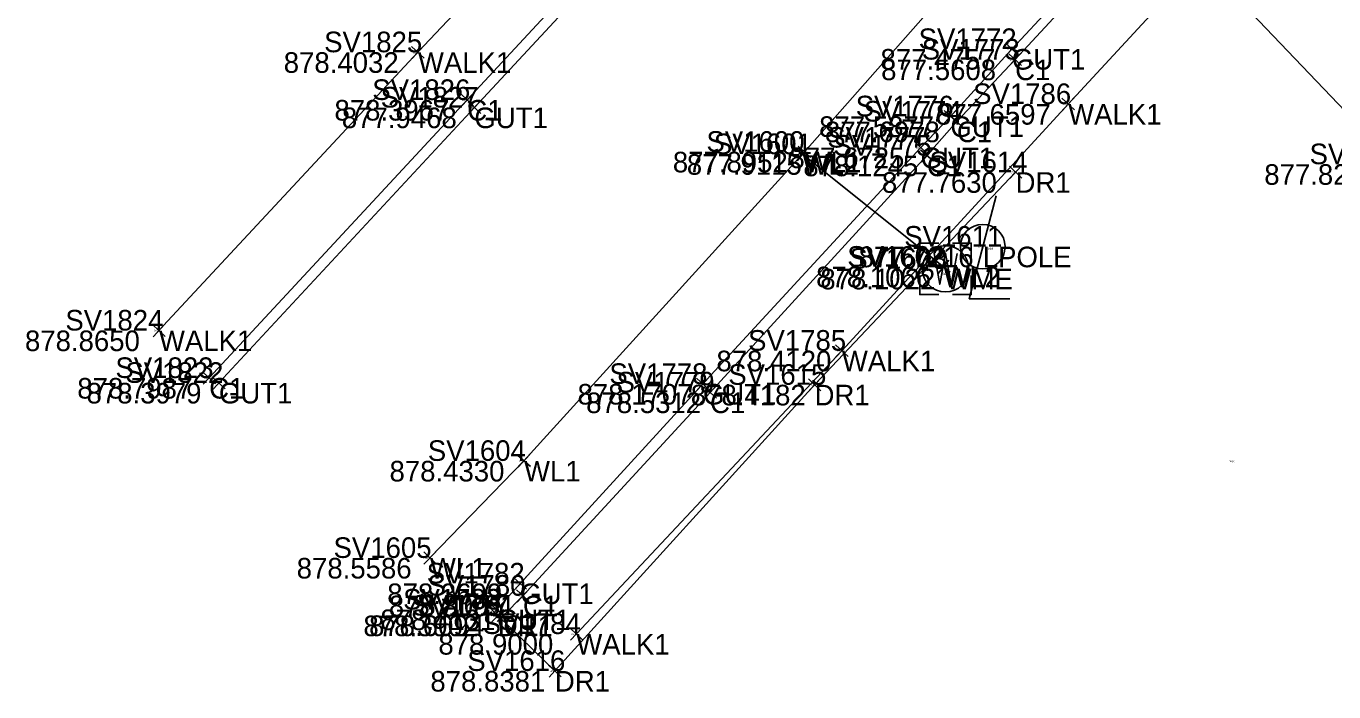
# Model space of a CAD drawing. Extents: x 1469677 to 1493262, y 375219 to 389293.
# Drawn here: x 1480027.7 to 1480103.9, y 379268.2 to 379307 of the extents above; entities that cross this region are included whole.
import ezdxf

# ---------------------------------------------------------------- set-up
doc = ezdxf.new("R2010")
doc.units = 0
for name, color, linetype in [('DR_X_Drive_Pipe', 7, 'Continuous'), ('DV_X_Lot_Line', 7, 'Continuous'), ('DV_X_Text', 7, 'Continuous'), ('GK_Visualization', 7, 'Continuous'), ('PNTDESC', 7, 'Continuous'), ('PNTELEV', 7, 'Continuous'), ('PNTNO', 7, 'Continuous'), ('RD_P_Text', 7, 'Continuous'), ('RW_P_Esmt_SW', 7, 'Continuous'), ('Text Border', 7, 'Continuous')]:
    doc.layers.add(name, color=color, linetype=linetype)

msp = doc.modelspace()

# ---------------------------------------------------------------- linework, layer by layer
at = {"layer": 'DR_X_Drive_Pipe'}
for points in [[(1480169.204, 379397.823), (1480165.761, 379394.087), (1480162.59, 379391.88), (1480159.156, 379388.706), (1480148.911, 379378.819), (1480120.344, 379350.087), (1480106.297, 379335.736), (1480080.736, 379308.289), (1480073.091, 379299.637), (1480056.748, 379281.628), (1480051.266, 379275.974)], [(1480072.97, 379299.499), (1480081.181, 379292.941)]]:
    msp.add_lwpolyline(points, dxfattribs=at)
at = {"layer": 'DV_X_Lot_Line'}
for points in [[(1480035.484, 379289.224), (1480050.568, 379305.437), (1480062.335, 379317.896), (1480064.038, 379319.719), (1480070.805, 379327.066), (1480078.054, 379334.946), (1480079.953, 379336.866), (1480094.208, 379352.393), (1480112.048, 379371.575), (1480117.348, 379377.211), (1480119.911, 379379.906), (1480121.511, 379381.77), (1480134.604, 379395.58), (1480136.695, 379398.148), (1480138.778, 379401.149), (1480140.004, 379404.725), (1480140.577, 379408.06), (1480140.982, 379411.311), (1480140.871, 379414.584), (1480140.225, 379417.636), (1480139.184, 379419.586), (1480133.124, 379425.845), (1480132.903, 379425.968), (1480114.834, 379442.96)], [(1480059.793, 379271.54), (1480075.261, 379288.048), (1480088.444, 379302.419), (1480096.088, 379310.695), (1480098.33, 379313.163), (1480111.975, 379327.613), (1480128.977, 379345.933), (1480145.46, 379363.52), (1480153.413, 379372.021), (1480155.772, 379374.786), (1480158.213, 379377.107), (1480160.137, 379378.801), (1480161.631, 379379.994)]]:
    msp.add_lwpolyline(points, dxfattribs=at)
at = {"layer": 'PNTDESC'}
msp.add_lwpolyline([(1480084.257, 379297.063), (1480082.682, 379291.078), (1480085.046, 379291.078)], dxfattribs=at)
msp.add_circle((1480083.471, 379294.11), 1.3, dxfattribs=at)
at = {"layer": 'PNTELEV'}
for p, q in [((1480050.202, 379305.777), (1480050.934, 379305.096)), ((1480050.227, 379305.071), (1480050.909, 379305.803)), ((1480050.568, 379305.437), (1480050.568, 379305.437)), ((1480085.532, 379305.284), (1480084.8, 379305.965)), ((1480085.507, 379305.99), (1480084.825, 379305.258)), ((1480085.723, 379304.67), (1480084.989, 379305.349)), ((1480085.696, 379305.377), (1480085.016, 379304.643)), ((1480085.166, 379305.624), (1480085.166, 379305.624)), ((1480085.356, 379305.01), (1480085.356, 379305.01)), ((1480053.105, 379302.289), (1480053.785, 379303.022)), ((1480053.079, 379302.996), (1480053.811, 379302.315)), ((1480053.445, 379302.656), (1480053.445, 379302.656)), ((1480053.491, 379302.555), (1480054.225, 379301.874)), ((1480053.518, 379301.848), (1480054.198, 379302.581)), ((1480088.076, 379302.757), (1480088.812, 379302.081)), ((1480088.106, 379302.051), (1480088.782, 379302.788)), ((1480088.444, 379302.419), (1480088.444, 379302.419)), ((1480053.858, 379302.215), (1480053.858, 379302.215)), ((1480081.954, 379301.365), (1480081.216, 379302.039)), ((1480081.922, 379302.071), (1480081.248, 379301.332)), ((1480081.585, 379301.702), (1480081.585, 379301.702)), ((1480082.332, 379301.055), (1480081.602, 379301.739)), ((1480082.309, 379301.762), (1480081.625, 379301.032)), ((1480081.967, 379301.397), (1480081.967, 379301.397)), ((1480073.465, 379299.306), (1480072.716, 379299.969)), ((1480073.422, 379300.012), (1480072.76, 379299.263)), ((1480080.216, 379299.537), (1480079.492, 379300.227)), ((1480080.199, 379300.244), (1480079.509, 379299.52)), ((1480072.579, 379299.811), (1480073.36, 379299.187)), ((1480073.282, 379299.889), (1480072.658, 379299.108)), ((1480072.97, 379299.499), (1480072.97, 379299.499)), ((1480073.091, 379299.637), (1480073.091, 379299.637)), ((1480080.593, 379299.082), (1480079.843, 379299.743)), ((1480079.854, 379299.882), (1480079.854, 379299.882)), ((1480080.549, 379299.788), (1480079.887, 379299.038)), ((1480080.218, 379299.413), (1480080.218, 379299.413)), ((1480085.747, 379298.104), (1480085.02, 379298.791)), ((1480085.727, 379298.811), (1480085.04, 379298.084)), ((1480085.383, 379298.448), (1480085.383, 379298.448)), ((1480080.791, 379293.253), (1480081.572, 379292.629)), ((1480081.493, 379293.332), (1480080.869, 379292.55)), ((1480081.181, 379292.941), (1480081.181, 379292.941)), ((1480035.118, 379289.565), (1480035.85, 379288.884)), ((1480035.143, 379288.858), (1480035.825, 379289.59)), ((1480035.484, 379289.224), (1480035.484, 379289.224)), ((1480074.896, 379288.39), (1480075.626, 379287.707)), ((1480074.919, 379287.684), (1480075.603, 379288.413)), ((1480075.261, 379288.048), (1480075.261, 379288.048)), ((1480038.043, 379286.798), (1480038.775, 379286.118)), ((1480038.069, 379286.092), (1480038.749, 379286.824)), ((1480038.409, 379286.458), (1480038.409, 379286.458)), ((1480038.612, 379286.514), (1480039.346, 379285.834)), ((1480038.639, 379285.807), (1480039.319, 379286.541)), ((1480067.54, 379285.772), (1480066.804, 379286.449)), ((1480067.511, 379286.478), (1480066.833, 379285.742)), ((1480074.037, 379285.718), (1480073.311, 379286.405)), ((1480074.017, 379286.425), (1480073.33, 379285.699)), ((1480038.979, 379286.174), (1480038.979, 379286.174)), ((1480067.172, 379286.11), (1480067.172, 379286.11)), ((1480067.958, 379285.276), (1480067.22, 379285.951)), ((1480067.927, 379285.982), (1480067.251, 379285.244)), ((1480067.589, 379285.613), (1480067.589, 379285.613)), ((1480073.674, 379286.062), (1480073.674, 379286.062)), ((1480057.118, 379281.292), (1480056.378, 379281.964)), ((1480057.084, 379281.999), (1480056.412, 379281.258)), ((1480056.748, 379281.628), (1480056.748, 379281.628)), ((1480051.624, 379275.625), (1480050.907, 379276.322)), ((1480051.614, 379276.332), (1480050.917, 379275.615)), ((1480051.266, 379275.974), (1480051.266, 379275.974)), ((1480056.869, 379274.854), (1480056.193, 379274.116)), ((1480056.9, 379274.147), (1480056.162, 379274.823)), ((1480057.056, 379273.435), (1480056.32, 379274.113)), ((1480057.027, 379274.142), (1480056.349, 379273.406)), ((1480056.531, 379274.485), (1480056.531, 379274.485)), ((1480055.541, 379272.635), (1480054.797, 379273.303)), ((1480055.503, 379273.341), (1480054.835, 379272.597)), ((1480056.688, 379273.774), (1480056.688, 379273.774)), ((1480055.577, 379272.265), (1480054.859, 379272.96)), ((1480054.87, 379272.253), (1480055.566, 379272.972)), ((1480055.169, 379272.969), (1480055.169, 379272.969)), ((1480055.902, 379272.271), (1480055.192, 379272.975)), ((1480055.899, 379272.978), (1480055.195, 379272.268)), ((1480055.218, 379272.613), (1480055.218, 379272.613)), ((1480055.547, 379272.623), (1480055.547, 379272.623)), ((1480059.428, 379271.882), (1480060.158, 379271.198)), ((1480059.451, 379271.175), (1480060.135, 379271.905)), ((1480059.793, 379271.54), (1480059.793, 379271.54)), ((1480058.916, 379269.052), (1480058.175, 379269.724)), ((1480058.881, 379269.758), (1480058.21, 379269.018)), ((1480058.546, 379269.388), (1480058.546, 379269.388))]:
    msp.add_line(p, q, dxfattribs=at)
at = {"layer": 'PNTNO'}
msp.add_line((1480081.303, 379292.82), (1480081.303, 379292.82), dxfattribs=at)
for points in [[(1480080.903, 379294.32), (1480079.803, 379294.32), (1480079.803, 379293.22)], [(1480082.803, 379293.22), (1480082.803, 379294.32), (1480081.703, 379294.32)], [(1480080.637, 379293.72), (1480080.97, 379291.92), (1480081.303, 379293.72), (1480081.637, 379291.92), (1480081.97, 379293.72)], [(1480079.803, 379292.42), (1480079.803, 379291.32), (1480080.903, 379291.32)], [(1480081.703, 379291.32), (1480082.803, 379291.32), (1480082.803, 379292.42)]]:
    msp.add_lwpolyline(points, dxfattribs=at)
msp.add_circle((1480081.303, 379292.82), 1.35, dxfattribs=at)
at = {"layer": 'RD_P_Text'}
for points in [[(1480155.238, 379379.795), (1480153.548, 379379.014), (1480146.824, 379371.927), (1480145.567, 379370.605), (1480143.964, 379368.78), (1480128.12, 379351.892), (1480112.56, 379335.214), (1480098.785, 379320.255), (1480094.793, 379316.092), (1480093.124, 379314.172), (1480085.166, 379305.624), (1480081.585, 379301.702), (1480079.854, 379299.882), (1480067.172, 379286.11), (1480056.531, 379274.485), (1480055.169, 379272.969)], [(1480155.431, 379379.884), (1480153.98, 379378.667), (1480147.216, 379371.505), (1480146.047, 379370.27), (1480144.119, 379368.047), (1480128.647, 379351.629), (1480112.741, 379334.357), (1480099.146, 379319.858), (1480095.569, 379316.008), (1480093.53, 379313.846), (1480085.356, 379305.01), (1480081.967, 379301.397), (1480080.218, 379299.413), (1480067.589, 379285.613), (1480056.688, 379273.774), (1480055.547, 379272.623)], [(1480038.409, 379286.458), (1480053.445, 379302.656), (1480065.083, 379315.224), (1480066.832, 379317.181), (1480073.782, 379324.407), (1480080.94, 379332.144), (1480082.529, 379333.877), (1480097.272, 379349.731)], [(1480038.979, 379286.174), (1480053.858, 379302.215), (1480065.464, 379314.71), (1480067.296, 379316.727), (1480074.111, 379324.008), (1480081.345, 379331.835), (1480082.794, 379333.357), (1480097.622, 379349.287)]]:
    msp.add_lwpolyline(points, dxfattribs=at)
at = {"layer": 'Text Border'}
for points in [[(1480096.199, 379310.793), (1480107.531, 379298.913)], [(1480085.383, 379298.448), (1480073.674, 379286.062), (1480058.546, 379269.388), (1480055.218, 379272.613)]]:
    msp.add_lwpolyline(points, dxfattribs=at)

# ---------------------------------------------------------------- texts
at = {"layer": 'DV_X_Text'}
for s, height, p in [('878.4032', 1.2, (1480042.754, 379304.237)), ('878.40', 0.06, (1480050.282, 379305.377)), ('877.4757', 1.2, (1480077.513, 379304.424)), ('877.48', 0.06, (1480084.886, 379305.564)), ('877.5608', 1.2, (1480077.552, 379303.81)), ('877.56', 0.06, (1480085.073, 379304.95)), ('878.3967', 1.2, (1480045.707, 379301.456)), ('878.40', 0.06, (1480053.159, 379302.596)), ('877.6597', 1.2, (1480080.744, 379301.219)), ('877.66', 0.06, (1480088.16, 379302.359)), ('877.9468', 1.2, (1480046.139, 379301.015)), ('877.95', 0.06, (1480053.578, 379302.155)), ('877.5877', 1.2, (1480073.941, 379300.502)), ('877.59', 0.06, (1480081.305, 379301.642)), ('877.6978', 1.2, (1480074.276, 379300.197)), ('877.70', 0.06, (1480081.684, 379301.337)), ('877.8952', 1.2, (1480065.419, 379298.437)), ('877.9115', 1.2, (1480066.234, 379298.299)), ('877.6725', 1.2, (1480072.21, 379298.682)), ('877.91', 0.06, (1480072.712, 379299.439)), ('877.90', 0.06, (1480072.806, 379299.577)), ('878.1245', 1.2, (1480073.019, 379298.213)), ('877.67', 0.06, (1480079.574, 379299.822)), ('878.12', 0.06, (1480079.962, 379299.353)), ('877.7630', 1.2, (1480077.598, 379297.248)), ('877.76', 0.06, (1480085.101, 379298.388)), ('877.8297', 1.2, (1480099.868, 379297.713)), ('877.7216', 1.2, (1480076.243, 379292.91)), ('877.72', 0.06, (1480083.193, 379294.05)), ('878.08', 0.06, (1480083.793, 379293.938)), ('878.08', 0.06, (1480083.793, 379293.938)), ('878.1066', 1.2, (1480073.765, 379291.741)), ('878.1022', 1.2, (1480074.01, 379291.62)), ('878.11', 0.06, (1480080.947, 379292.881)), ('878.10', 0.06, (1480081.041, 379292.76)), ('878.17', 0.06, (1480081.073, 379292.465)), ('878.8650', 1.2, (1480027.68, 379288.024)), ('878.87', 0.06, (1480035.204, 379289.164)), ('878.4120', 1.2, (1480067.958, 379286.848)), ('878.41', 0.06, (1480075.003, 379287.988)), ('878.7987', 1.2, (1480030.728, 379285.258)), ('878.80', 0.06, (1480038.124, 379286.398)), ('878.3979', 1.2, (1480031.269, 379284.974)), ('878.40', 0.06, (1480038.693, 379286.114)), ('878.1707', 1.2, (1480059.869, 379284.91)), ('878.5312', 1.2, (1480060.371, 379284.413)), ('878.4182', 1.2, (1480066.466, 379284.862)), ('878.17', 0.06, (1480066.916, 379286.05)), ('878.53', 0.06, (1480067.309, 379285.553)), ('878.42', 0.06, (1480073.394, 379286.002)), ('878.4330', 1.2, (1480048.915, 379280.428)), ('878.43', 0.06, (1480056.467, 379281.568)), ('878.08', 0.06, (1480097.868, 379281.538)), ('878.5586', 1.2, (1480043.509, 379274.774)), ('878.56', 0.06, (1480050.982, 379275.914)), ('878.3699', 1.2, (1480048.783, 379273.285)), ('878.37', 0.06, (1480056.25, 379274.425)), ('878.8095', 1.2, (1480048.874, 379272.574)), ('878.81', 0.06, (1480056.43, 379273.714)), ('878.3902', 1.2, (1480047.395, 379271.413)), ('878.6094', 1.2, (1480047.724, 379271.423)), ('878.4131', 1.2, (1480048.384, 379271.769)), ('878.41', 0.06, (1480054.911, 379272.909)), ('878.39', 0.06, (1480054.936, 379272.553)), ('878.61', 0.06, (1480055.288, 379272.563)), ('878.9000', 1.2, (1480051.762, 379270.34)), ('878.90', 0.06, (1480059.507, 379271.48)), ('878.8381', 1.2, (1480051.296, 379268.188)), ('878.84', 0.06, (1480058.266, 379269.328))]:
    msp.add_text(s, height=height, dxfattribs=at).set_placement(p)
at = {"layer": 'GK_Visualization'}
for s, p in [('WALK1', (1480050.568, 379304.237)), ('GUT1', (1480085.166, 379304.424)), ('C1', (1480085.356, 379303.81)), ('C1', (1480053.445, 379301.456)), ('WALK1', (1480088.444, 379301.219)), ('GUT1', (1480053.858, 379301.015)), ('GUT1', (1480081.585, 379300.502)), ('C1', (1480081.967, 379300.197)), ('WL2', (1480072.97, 379298.299)), ('WL1', (1480073.091, 379298.437)), ('GUT1', (1480079.854, 379298.682)), ('C1', (1480080.218, 379298.213)), ('DR1', (1480085.383, 379297.248)), ('LPOLE', (1480083.471, 379292.91)), ('WL2', (1480081.181, 379291.741)), ('WME', (1480081.303, 379291.62)), ('WALK1', (1480035.484, 379288.024)), ('WALK1', (1480075.261, 379286.848)), ('C1', (1480038.409, 379285.258)), ('GUT1', (1480038.979, 379284.974)), ('GUT1', (1480067.172, 379284.91)), ('C1', (1480067.589, 379284.413)), ('DR1', (1480073.674, 379284.862)), ('WL1', (1480056.748, 379280.428)), ('WL1', (1480051.266, 379274.774)), ('GUT1', (1480056.531, 379273.285)), ('C1', (1480056.688, 379272.574)), ('GUT1', (1480055.169, 379271.769)), ('DR1', (1480055.218, 379271.413)), ('C1', (1480055.547, 379271.423)), ('WALK1', (1480059.793, 379270.34)), ('DR1', (1480058.546, 379268.188))]:
    msp.add_text(s, height=1.2, dxfattribs=at).set_placement(p)
at = {"layer": 'RW_P_Esmt_SW'}
for s, height, p in [('SV1772', 1.2, (1480079.734, 379305.624)), ('SV1825', 1.2, (1480045.108, 379305.437)), ('SV1773', 1.2, (1480079.915, 379305.01)), ('SV1825', 0.06, (1480050.295, 379305.437)), ('SV1772', 0.06, (1480084.894, 379305.624)), ('SV1773', 0.06, (1480085.084, 379305.01)), ('SV1826', 1.2, (1480047.909, 379302.656)), ('SV1827', 1.2, (1480048.398, 379302.215)), ('SV1786', 1.2, (1480082.908, 379302.419)), ('SV1826', 0.06, (1480053.168, 379302.656)), ('SV1827', 0.06, (1480053.585, 379302.215)), ('SV1776', 1.2, (1480076.068, 379301.702)), ('SV1774', 1.2, (1480076.535, 379301.397)), ('SV1786', 0.06, (1480088.167, 379302.419)), ('SV1776', 0.06, (1480081.309, 379301.702)), ('SV1600', 1.2, (1480067.375, 379299.637)), ('SV1777', 1.2, (1480074.413, 379299.882)), ('SV1774', 0.06, (1480081.695, 379301.397)), ('SV1601', 1.2, (1480067.809, 379299.499)), ('SV1775', 1.2, (1480074.777, 379299.413)), ('SV1613', 1.2, (1480102.506, 379298.913)), ('SV1601', 0.06, (1480072.712, 379299.499)), ('SV1600', 0.06, (1480072.805, 379299.637)), ('SV1777', 0.06, (1480079.582, 379299.882)), ('SV1775', 0.06, (1480079.946, 379299.413)), ('SV1614', 1.2, (1480080.368, 379298.448)), ('SV1614', 0.06, (1480085.132, 379298.448)), ('SV1611', 1.2, (1480078.897, 379294.11)), ('SV1602', 1.2, (1480075.579, 379292.941)), ('SV1603', 1.2, (1480075.692, 379292.82)), ('SV1611', 0.06, (1480083.242, 379294.11)), ('SA2088', 0.06, (1480083.777, 379293.998)), ('SA2089', 0.06, (1480083.777, 379293.998)), ('SV1602', 0.06, (1480080.901, 379292.941)), ('SV1603', 0.06, (1480081.022, 379292.82)), ('SA2087', 0.06, (1480081.027, 379292.525)), ('SV1824', 1.2, (1480030.033, 379289.224)), ('SV1824', 0.06, (1480035.211, 379289.224)), ('SV1785', 1.2, (1480069.801, 379288.048)), ('SV1785', 0.06, (1480074.988, 379288.048)), ('SV1823', 1.2, (1480032.949, 379286.458)), ('SV1822', 1.2, (1480033.528, 379286.174)), ('SV1778', 1.2, (1480061.721, 379286.11)), ('SV1615', 1.2, (1480068.649, 379286.062)), ('SV1823', 0.06, (1480038.136, 379286.458)), ('SV1779', 1.2, (1480062.138, 379285.613)), ('SV1822', 0.06, (1480038.706, 379286.174)), ('SV1778', 0.06, (1480066.899, 379286.11)), ('SV1779', 0.06, (1480067.316, 379285.613)), ('SV1615', 0.06, (1480073.423, 379286.062)), ('SV1604', 1.2, (1480051.146, 379281.628)), ('SV1604', 0.06, (1480056.468, 379281.628)), ('SA2002', 0.06, (1480097.847, 379281.598)), ('SV1605', 1.2, (1480045.654, 379275.974)), ('SV1605', 0.06, (1480050.985, 379275.974)), ('SV1782', 1.2, (1480051.08, 379274.485)), ('SV1780', 1.2, (1480051.124, 379273.774)), ('SV1783', 1.2, (1480049.709, 379272.969)), ('SV1782', 0.06, (1480056.258, 379274.485)), ('SV1617', 1.2, (1480050.193, 379272.613)), ('SV1781', 1.2, (1480050.538, 379272.623)), ('SV1780', 0.06, (1480056.41, 379273.774)), ('SV1784', 1.2, (1480054.342, 379271.54)), ('SV1783', 0.06, (1480054.896, 379272.969)), ('SV1617', 0.06, (1480054.967, 379272.613)), ('SV1781', 0.06, (1480055.297, 379272.623)), ('SV1784', 0.06, (1480059.52, 379271.54)), ('SV1616', 1.2, (1480053.445, 379269.388)), ('SV1616', 0.06, (1480058.291, 379269.388))]:
    msp.add_text(s, height=height, dxfattribs=at).set_placement(p)

doc.saveas('drawing.dxf')
